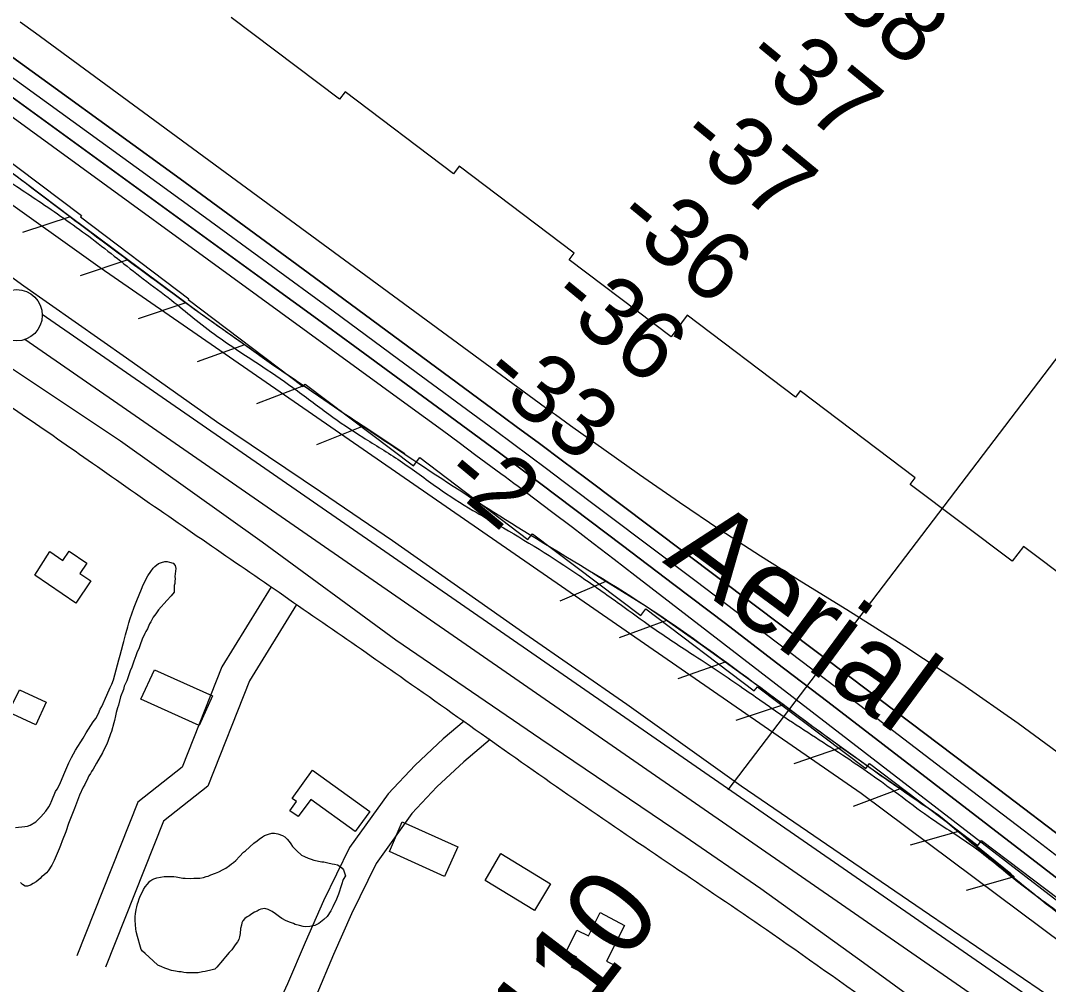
# Model space of a CAD drawing. Extents: x 3887375 to 3925618, y 296674 to 322633.
# Drawn here: x 3892222 to 3893221, y 311534 to 312470 of the extents above; entities that cross this region are included whole.
import ezdxf

# ---------------------------------------------------------------- set-up
doc = ezdxf.new("R2010")
doc.units = 0
for name, color, linetype in [('V-BLDG-OTLN', 7, 'Continuous'), ('V-LEVE-TOET', 7, 'Continuous'), ('V-RIVR-EDGE', 7, 'Continuous'), ('V-RIVR-IDEN', 7, 'Continuous'), ('V-RIVR-RANG', 7, 'Continuous'), ('V-RIVR-RANG-IDEN', 7, 'Continuous'), ('V-ROAD-CNTR', 7, 'Continuous'), ('V-RRAP-FSHR', 7, 'Continuous'), ('V-RRAP-RVMT', 7, 'Continuous'), ('V-SITE-VEGE', 7, 'Continuous'), ('V-SURV-LINE', 7, 'Continuous'), ('V-TOPO-DPTH', 7, 'Continuous'), ('V-TOPO-MINR', 7, 'Continuous')]:
    doc.layers.add(name, color=color, linetype=linetype)

msp = doc.modelspace()

# ---------------------------------------------------------------- linework, layer by layer
at = {"layer": 'V-BLDG-OTLN'}
for points in [[(3892236.46, 311931.08), (3892250.99, 311954.13), (3892263.64, 311945.47), (3892269.81, 311954.48), (3892286.89, 311942.78), (3892280.11, 311932.88), (3892290.85, 311925.52), (3892276.07, 311903.94)], [(3892352.7, 311839.17), (3892408.97, 311813.8), (3892396.08, 311785.19), (3892339.51, 311810.69)], [(3892221.56, 311819.8), (3892247.45, 311807.8), (3892237.28, 311785.86), (3892210.85, 311798.12)], [(3892561.98, 311701.53), (3892547.62, 311682.19), (3892504.42, 311713.3), (3892492.35, 311696.54), (3892484.31, 311702.33), (3892490.7, 311711.19), (3892486.37, 311714.3), (3892506.14, 311741.75)], [(3892593.35, 311691.52), (3892647.36, 311667.2), (3892634.4, 311638.43), (3892580.85, 311662.54)], [(3892673.97, 311634.35), (3892689.05, 311660.58), (3892737.52, 311631.4), (3892721.91, 311605.48)], [(3892809.42, 311590.93), (3892792.01, 311556.2), (3892802.45, 311550.96), (3892794.51, 311535.11), (3892782.81, 311540.98), (3892781.54, 311538.46), (3892757.98, 311550.26), (3892762.9, 311560.06), (3892752.57, 311565.23), (3892763.12, 311586.27), (3892774.26, 311580.69), (3892785.71, 311603.53)]]:
    msp.add_lwpolyline(points, close=True, dxfattribs=at)
at = {"layer": 'V-LEVE-TOET'}
for points in [[(3891470.84, 312662.89), (3891560.54, 312610.95), (3891672.72, 312538.88), (3891789.15, 312457.06), (3891908.44, 312364.28), (3891989.87, 312296.2), (3892058.03, 312243.98), (3892194.92, 312144.74), (3892319.54, 312061.78), (3892457.42, 311963.54), (3892587.1, 311868.44), (3892728.16, 311772.22), (3892868.41, 311677.19), (3892941.75, 311626.8), (3893041.76, 311554.85), (3893157.21, 311470.62), (3893331.95, 311347.69), (3893386.65, 311309.75), (3893477.31, 311234.74), (3893652.21, 311086.68), (3893804.29, 310952.63), (3893919.11, 310842.87), (3893996.64, 310761.99)], [(3894071.67, 310798.13), (3893995, 310874), (3893912.31, 310958.98), (3893872.09, 310996.1), (3893832.49, 311030.65), (3893774.46, 311077.88), (3893657.88, 311175.96), (3893542.29, 311273.85), (3893422.69, 311375.69), (3893387.3, 311405.29), (3893373.9, 311415.94), (3893344.14, 311437.02), (3893212.28, 311528.44), (3893105.6, 311601.13), (3893018.9, 311660.42), (3892922.81, 311726.22), (3892811.52, 311805.64), (3892712.43, 311874.2), (3892583.76, 311964.64), (3892514.04, 312012.12), (3892412.96, 312080.27), (3892325.45, 312142.14), (3892225.56, 312211.89), (3892134.64, 312277.73)]]:
    msp.add_lwpolyline(points, dxfattribs=at)
at = {"layer": 'V-RIVR-EDGE'}
msp.add_spline([(3891467.98, 312833.96), (3891486.98, 312822.05), (3891534.01, 312792.8), (3891594.13, 312753.8), (3891650.38, 312718.69), (3891687.23, 312694.81), (3891715.84, 312678.71), (3891775.97, 312641.17), (3891829.3, 312607.04), (3891872.45, 312576.34), (3891897.65, 312554.91), (3891920.44, 312540.28), (3891948.54, 312515.93), (3892002.83, 312474.52), (3892042.08, 312440.43), (3892073.59, 312415.58), (3892102.19, 312395.6), (3892133.21, 312371.24), (3892200.11, 312321.54), (3892242.77, 312292.79), (3892291.73, 312258.18), (3892341.66, 312219.21), (3892369.29, 312198.26), (3892390.13, 312181.21), (3892413.88, 312163.18), (3892453.63, 312136.38), (3892487.09, 312113.47), (3892521.99, 312087.64), (3892554.96, 312065.22), (3892591.32, 312042.31), (3892628.16, 312015.99), (3892662.1, 311994.06), (3892686.84, 311979.91), (3892764.9, 311931.15), (3892805.14, 311902.89), (3892836.17, 311880.47), (3892877.86, 311852.69), (3892924.41, 311821.49), (3892965.13, 311793.23), (3893024.77, 311754.23), (3893079.06, 311715.73), (3893108.15, 311694.29), (3893146.45, 311668.94), (3893184.74, 311638.74), (3893227.88, 311606.09), (3893285.08, 311562.73), (3893338.89, 311523.75), (3893381.55, 311493.05), (3893441.66, 311449.68), (3893482.38, 311419.95), (3893505.63, 311395.61), (3893524.53, 311379.05), (3893555.07, 311358.1), (3893588.51, 311330.33), (3893620.5, 311305.49), (3893676.23, 311256.3), (3893730.02, 311212.46), (3893771.69, 311174.96), (3893804.16, 311145.26), (3893965.04, 311005.48), (3893991.69, 310979.19), (3894015.41, 310950.48), (3894041.09, 310924.19), (3894068.7, 310897.9)], degree=3, dxfattribs=at)
at = {"layer": 'V-RIVR-RANG'}
msp.add_line((3892910.08, 311722.47), (3893249.22, 312168.1), dxfattribs=at)
at = {"layer": 'V-ROAD-CNTR'}
for points in [[(3892465.97, 311919.7), (3892418.1, 311841.98), (3892379.53, 311744.67), (3892336.49, 311710.63), (3892277.18, 311561.2)], [(3892490.67, 311902.6), (3892445.02, 311828.49), (3892404.46, 311726.13), (3892361.41, 311692.09), (3892305.06, 311550.13)], [(3892653.42, 311789.44), (3892633.21, 311772.21), (3892605.79, 311746.62), (3892579.59, 311718.63), (3892542.28, 311666.44), (3892516.84, 311614.88), (3892498.98, 311574.38), (3892481.93, 311534.01), (3892467.13, 311501.72), (3892460.06, 311465.88), (3892464.09, 311419.86)], [(3892678.71, 311771.58), (3892653.19, 311749.82), (3892627, 311725.37), (3892602.84, 311699.57), (3892568.11, 311650.98), (3892544.03, 311602.19), (3892526.53, 311562.49), (3892509.39, 311521.92), (3892495.87, 311492.44), (3892490.31, 311464.26), (3892493.97, 311422.48)]]:
    msp.add_lwpolyline(points, dxfattribs=at)
msp.add_spline([(3891930.71, 312305.17), (3892016.94, 312237.42), (3892090.97, 312173.45), (3892154.3, 312132.93), (3892292.49, 312039.88), (3892440.64, 311937.24), (3892591.28, 311832.93), (3892771.43, 311706.32), (3892952.89, 311582.91), (3893068.84, 311500.71)], degree=3, dxfattribs=at)
at = {"layer": 'V-RRAP-FSHR'}
for p, q in [((3892270.78, 312279.32), (3892224.38, 312264.11)), ((3892326.86, 312237.43), (3892280.55, 312221.93)), ((3892383.13, 312195.79), (3892336.83, 312180.3)), ((3892439.97, 312154.95), (3892393.96, 312138.6)), ((3892497.45, 312115), (3892451.79, 312097.69)), ((3892555.48, 312075.86), (3892510.06, 312057.94)), ((3892791.37, 311925.07), (3892746.45, 311905.94)), ((3892850.11, 311887.03), (3892804.27, 311870.2)), ((3892907.26, 311846.61), (3892861.13, 311830.58)), ((3892963.73, 311805.26), (3892917.4, 311789.82)), ((3893020.19, 311763.88), (3892974.05, 311747.89)), ((3893077.31, 311723.43), (3893031.54, 311706.41)), ((3893133.8, 311682.17), (3893086.86, 311668.72)), ((3893188.19, 311638.11), (3893141.25, 311624.65))]:
    msp.add_line(p, q, dxfattribs=at)
for points in [[(3891468.38, 312810.08), (3891592.07, 312735.45), (3892299.93, 312230.23), (3893039.21, 311719.28), (3893631.65, 311277.12), (3894117.75, 310846), (3894636.93, 310371.58), (3895241.96, 309786.83), (3895348.82, 309658.26), (3895604.32, 309398.25), (3896430.18, 308555.06), (3897023.94, 307973.73), (3897641.56, 307335.08), (3898033.61, 306930.91), (3898562.18, 306317.87), (3899280.35, 305434.23), (3899629.7, 304981.52), (3900046.19, 304414.8), (3900422.65, 303959.37), (3901188.76, 303011.8), (3901775.81, 302279.78)], [(3892270.78, 312279.32), (3892228.16, 312311.27), (3892214.81, 312321.36)], [(3892326.86, 312237.43), (3892312.36, 312248.16), (3892270.78, 312279.32)], [(3892383.13, 312195.79), (3892326.86, 312237.43)], [(3892439.97, 312154.95), (3892396.96, 312185.57), (3892383.13, 312195.79)], [(3892497.45, 312115), (3892466.5, 312136.07), (3892439.97, 312154.95)], [(3892555.48, 312075.86), (3892537.08, 312088.03), (3892497.45, 312115)], [(3892595.83, 312049.2), (3892555.48, 312075.86)], [(3892791.37, 311925.07), (3892779.01, 311932.78)], [(3892850.11, 311887.03), (3892830.41, 311900.74), (3892791.37, 311925.07)], [(3892907.26, 311846.61), (3892882.78, 311864.28), (3892850.11, 311887.03)], [(3892963.73, 311805.26), (3892934.52, 311826.93), (3892907.25, 311846.61)], [(3893020.19, 311763.88), (3892992.52, 311783.9), (3892963.73, 311805.26)], [(3893077.31, 311723.43), (3893051.01, 311741.57), (3893020.19, 311763.88)], [(3893188.19, 311638.11), (3893184.85, 311640.81), (3893133.8, 311682.17), (3893114.78, 311697.57), (3893082.89, 311719.57), (3893077.31, 311723.43)]]:
    msp.add_lwpolyline(points, dxfattribs=at)
for points in [[(3893114.78, 311697.57), (3893051.01, 311741.57), (3892934.52, 311826.93), (3892830.41, 311900.74), (3892716.58, 311970.79), (3892537.08, 312088.03), (3892396.96, 312185.57), (3892228.16, 312311.27), (3892082.04, 312421.65), (3891952.19, 312519.08)], [(3894693.57, 310343.47), (3894636.16, 310402.03), (3894583.88, 310450.27), (3894539.33, 310488.07), (3894475.19, 310544.65), (3894335.29, 310653.91), (3894243.97, 310732.33), (3894177.91, 310791.34), (3894063.4, 310901.68), (3893962.88, 310997.56), (3893817.75, 311132.76), (3893736.38, 311204.28), (3893588.1, 311328.9), (3893395.57, 311482.54), (3893254.93, 311584.04), (3893114.78, 311697.57)]]:
    msp.add_spline(points, degree=3, dxfattribs=at)
at = {"layer": 'V-RRAP-RVMT'}
for p, q in [((3892532.53, 312393.54), (3892427.21, 312473.14)), ((3892537.92, 312400.85), (3892532.53, 312393.54)), ((3892643.31, 312321.22), (3892537.92, 312400.85)), ((3892182.7, 312355.27), (3892281.63, 312280.54)), ((3892648.7, 312328.46), (3892643.31, 312321.22)), ((3892760.45, 312243.93), (3892648.7, 312328.46)), ((3892281.63, 312280.54), (3892280.67, 312279.33)), ((3892280.67, 312279.33), (3892385.9, 312199.67)), ((3892755.75, 312237.59), (3892760.45, 312243.93)), ((3892854.64, 312162.86), (3892755.75, 312237.59)), ((3892385.9, 312199.67), (3892385.41, 312198.95)), ((3892385.41, 312198.95), (3892497.11, 312114.56)), ((3892870.34, 312183.74), (3892854.64, 312162.86)), ((3892975.59, 312104.1), (3892870.34, 312183.74)), ((3892497.11, 312114.56), (3892498.98, 312116.91)), ((3892498.98, 312116.91), (3892604.25, 312037.4)), ((3892980.22, 312110.17), (3892975.59, 312104.1)), ((3893091.83, 312025.72), (3892980.22, 312110.17)), ((3892604.25, 312037.4), (3892610.4, 312045.46)), ((3892610.4, 312045.46), (3892715.53, 311965.82)), ((3893087.06, 312019.38), (3893091.83, 312025.72)), ((3893186.02, 311944.71), (3893087.06, 312019.38)), ((3892715.53, 311965.82), (3892719.89, 311971.47)), ((3892719.89, 311971.47), (3892825.22, 311891.9)), ((3893196.94, 311959.04), (3893186.02, 311944.71)), ((3893302.33, 311879.48), (3893196.94, 311959.04)), ((3892825.22, 311891.9), (3892830.06, 311898.31)), ((3892830.06, 311898.31), (3892935.4, 311818.8)), ((3892935.4, 311818.8), (3892938.51, 311822.8)), ((3892938.51, 311822.8), (3893043.77, 311743.16)), ((3893043.77, 311743.16), (3893047.44, 311748.05)), ((3893047.44, 311748.05), (3893152.74, 311668.48)), ((3893152.74, 311668.48), (3893156.4, 311673.3)), ((3893156.4, 311673.3), (3893255.3, 311598.5))]:
    msp.add_line(p, q, dxfattribs=at)
at = {"layer": 'V-SITE-VEGE'}
for points in [[(3892275.89, 311761.12), (3892283.48, 311772.8), (3892286.08, 311777.84), (3892293.15, 311788.72), (3892295.5, 311791.91), (3892298.12, 311796.68), (3892299.94, 311800.92), (3892301.51, 311803.57), (3892306.19, 311814.7), (3892309.58, 311822.13), (3892311.14, 311825.31), (3892312.7, 311829.55), (3892318.13, 311848.87), (3892319.15, 311853.37), (3892320.44, 311858.4), (3892322.25, 311864.49), (3892322.76, 311866.87), (3892324.57, 311873.23), (3892325.08, 311875.61), (3892326.64, 311880.9), (3892327.67, 311884.88), (3892328.96, 311889.11), (3892330.52, 311893.61), (3892332.85, 311899.97), (3892335.45, 311906.6), (3892339.87, 311917.72), (3892341.7, 311921.7), (3892346.13, 311930.45), (3892349.01, 311934.7), (3892351.37, 311937.88), (3892352.94, 311939.48), (3892356.63, 311942.41), (3892359.53, 311943.48), (3892362.69, 311944.3), (3892364.81, 311944.31), (3892367.19, 311943.8), (3892370.63, 311942.77), (3892372.76, 311940.4), (3892373.31, 311937.5), (3892372.3, 311929.83), (3892372.58, 311927.72), (3892372.33, 311925.34), (3892372.34, 311923.22), (3892371.83, 311921.1), (3892371.84, 311918.73), (3892371.6, 311914.76)], [(3892371.6, 311914.76), (3892368.72, 311911.04), (3892364.79, 311906.52), (3892356.66, 311897.48), (3892355.34, 311895.63), (3892354.04, 311893.5), (3892351.42, 311890.31), (3892349.07, 311885.81), (3892347.76, 311883.95), (3892345.68, 311878.91), (3892344.11, 311876.53), (3892343.33, 311874.41), (3892340.72, 311868.84), (3892338.64, 311863.54), (3892337.6, 311860.63), (3892335.52, 311855.86), (3892334.48, 311852.68), (3892332.4, 311847.64), (3892330.59, 311841.82), (3892329.03, 311838.11), (3892325.66, 311828.57), (3892323.31, 311823.27), (3892322.54, 311820.1), (3892319.68, 311812.94), (3892317.62, 311805), (3892316.58, 311802.35), (3892315.29, 311797.59), (3892314.78, 311794.41), (3892313.75, 311789.91), (3892312.98, 311787.53), (3892310.92, 311779.32), (3892309.87, 311776.94), (3892307.28, 311769.52), (3892305.98, 311766.34), (3892303.89, 311762.1), (3892302.06, 311758.65), (3892296.32, 311748.57), (3892293.19, 311742.74), (3892291.35, 311740.35), (3892290.57, 311738.49), (3892288.74, 311736.1), (3892287.96, 311733.98), (3892284.83, 311727.89), (3892283.26, 311725.23), (3892279.87, 311717.28), (3892274.94, 311704.3), (3892268.96, 311689.73), (3892266.37, 311681.78), (3892262.98, 311673.04), (3892261.43, 311668.54), (3892260.13, 311665.36), (3892255.18, 311653.96), (3892254.14, 311651.84), (3892252.83, 311649.45), (3892249.44, 311643.88), (3892247.6, 311642.02), (3892244.97, 311639.62), (3892242.87, 311638.03), (3892241.56, 311636.43), (3892239.45, 311634.83), (3892237.61, 311633.23), (3892234.72, 311631.63), (3892232.08, 311630.03), (3892229.18, 311628.95), (3892226.81, 311628.94), (3892224.42, 311630.51), (3892222.29, 311632.61)], [(3892217.71, 311685.96), (3892226.69, 311686.81), (3892229.07, 311687.35), (3892231.7, 311688.16), (3892237.23, 311691.37), (3892242.22, 311696.42), (3892246.94, 311702.01), (3892249.82, 311705.99), (3892251.13, 311708.37), (3892252.95, 311712.09), (3892256.6, 311720.83), (3892258.16, 311723.22), (3892260.78, 311727.99), (3892264.42, 311737.53), (3892266.5, 311742.04), (3892269.36, 311748.92), (3892271.97, 311753.96), (3892275.89, 311761.12)], [(3892393.51, 311636.63), (3892396.68, 311636.92), (3892400.37, 311637.47), (3892402.75, 311638.28), (3892404.86, 311638.82), (3892407.49, 311639.9), (3892411.97, 311641.51), (3892415.14, 311642.85), (3892419.35, 311645.26), (3892421.98, 311646.6), (3892425.67, 311649), (3892427.5, 311650.6), (3892429.35, 311651.93), (3892431.71, 311654.06), (3892435.39, 311657.78), (3892439.06, 311662.03), (3892441.16, 311663.37), (3892449.31, 311670.82), (3892452.46, 311672.96), (3892454.3, 311674.55), (3892457.46, 311676.95), (3892459.56, 311678.29), (3892463.52, 311679.37), (3892466.69, 311680.45), (3892469.33, 311680.47), (3892472.5, 311679.96), (3892477.01, 311678.14), (3892479.39, 311676.83), (3892481.52, 311674.73), (3892483.65, 311672.37), (3892484.99, 311670.26), (3892486.86, 311667.63), (3892490.85, 311663.43), (3892495.63, 311659.23), (3892498.55, 311657.66), (3892501.99, 311656.1), (3892504.9, 311655.33), (3892507.55, 311654.29), (3892515.23, 311652.75), (3892517.34, 311652.5), (3892521.05, 311651.73), (3892525.28, 311650.71), (3892527.4, 311650.45), (3892530.58, 311649.68), (3892532.96, 311648.11), (3892535.09, 311646.54), (3892536.16, 311644.7), (3892538.31, 311639.16)], [(3892538.31, 311639.16), (3892535.95, 311635.45), (3892534.4, 311630.15), (3892531.55, 311621.15), (3892528.95, 311614.79), (3892526.86, 311611.08), (3892526.08, 311608.96), (3892524, 311604.98), (3892520.33, 311599.67), (3892517.18, 311596.48), (3892512.45, 311592.75), (3892508.5, 311590.87), (3892503.48, 311589.78), (3892499.52, 311589.49), (3892497.14, 311589.74), (3892493.7, 311590.78), (3892489.46, 311591.81), (3892487.61, 311592.59), (3892484.7, 311593.62), (3892480.45, 311595.45), (3892476.48, 311597.53), (3892474.09, 311599.11), (3892470.1, 311602.25), (3892466.92, 311604.34), (3892462.94, 311606.17), (3892459.77, 311607.2), (3892456.07, 311606.65), (3892454.23, 311605.84), (3892452.38, 311604.78), (3892449.75, 311603.7), (3892447.12, 311602.1), (3892444.48, 311600.23), (3892442.64, 311599.16), (3892440.54, 311597.56), (3892438.44, 311595.43), (3892437.66, 311593.32), (3892437.15, 311591.2), (3892436.11, 311587.76), (3892435.88, 311583), (3892435.37, 311579.82), (3892434.59, 311577.18), (3892433.29, 311574.79), (3892430.93, 311571.87), (3892427.79, 311567.09), (3892425.16, 311564.43), (3892421.49, 311560.18), (3892420.18, 311558.32), (3892418.87, 311556.73), (3892413.36, 311550.35), (3892411.26, 311548.48), (3892408.62, 311547.67), (3892402.03, 311546.04), (3892399.39, 311545.76), (3892395.16, 311544.94), (3892392.52, 311544.66), (3892388.29, 311544.63), (3892383.8, 311544.87), (3892381.16, 311545.11), (3892378.51, 311545.62), (3892376.13, 311545.88), (3892372.96, 311546.38), (3892369.25, 311547.15), (3892364.75, 311548.71), (3892362.63, 311549.22), (3892359.71, 311550.52), (3892356, 311552.35), (3892351.22, 311556.28), (3892343.51, 311563.63), (3892340.85, 311565.73), (3892339.78, 311567.57), (3892338.98, 311569.68), (3892336, 311579.97), (3892334.91, 311584.98), (3892334.63, 311587.62), (3892334.08, 311591.32), (3892333.79, 311595.81), (3892333.76, 311599.51), (3892334.27, 311602.15), (3892334.77, 311606.39), (3892335.55, 311608.77), (3892336.06, 311611.68), (3892336.84, 311613.54), (3892337.61, 311616.71), (3892339.18, 311619.89), (3892340.22, 311622.28), (3892342.04, 311625.73), (3892343.61, 311628.38), (3892345.71, 311630.77), (3892348.07, 311633.69), (3892350.18, 311635.29), (3892352.02, 311636.1), (3892354.92, 311637.17), (3892362.05, 311638.28), (3892371.3, 311638.34), (3892373.68, 311638.09), (3892376.85, 311637.31), (3892380.29, 311636.81), (3892382.41, 311636.82), (3892387.17, 311636.33), (3892390.86, 311636.61), (3892393.51, 311636.63)]]:
    msp.add_lwpolyline(points, dxfattribs=at)
at = {"layer": 'V-SURV-LINE'}
for points in [[(3892243.54, 312184.7), (3893320.18, 311440.26)], [(3893303.12, 311415.58), (3892226.48, 312160.02)]]:
    msp.add_lwpolyline(points, dxfattribs=at)
msp.add_circle((3892218.58, 312183.72), 25, dxfattribs=at)
at = {"layer": 'V-TOPO-DPTH'}
for points in [[(3892173.55, 312463.92), (3892252.5, 312406.87), (3892315.03, 312361.56), (3892377.47, 312316.12), (3892439.78, 312270.51), (3892502, 312224.78), (3892681.57, 312092.42), (3892704.17, 312075.71), (3892726.74, 312058.96), (3892749.26, 312042.14), (3892771.74, 312025.28), (3893029.68, 311831.28), (3893101.32, 311777.26), (3893172.86, 311723.12), (3893244.27, 311668.81)], [(3893244.27, 311668.81), (3893172.86, 311723.12), (3893101.32, 311777.26), (3893029.68, 311831.28), (3892771.74, 312025.28), (3892749.26, 312042.14), (3892726.74, 312058.96), (3892704.17, 312075.71), (3892681.57, 312092.42), (3892502, 312224.78), (3892439.78, 312270.51), (3892377.47, 312316.12), (3892315.03, 312361.56), (3892252.5, 312406.87), (3892173.55, 312463.92)], [(3892222.2, 312468.93), (3892237, 312458.09), (3892737.33, 312090.67), (3892742.19, 312087.12), (3892747.06, 312083.59), (3892751.95, 312080.07), (3892756.85, 312076.58), (3892824.07, 312028.88), (3892862.85, 312001.94), (3892901.97, 311975.53), (3892941.62, 311949.91), (3892981.62, 311924.82), (3893025.48, 311897.91), (3893081.76, 311862.26), (3893137.32, 311825.57), (3893191.81, 311787.3), (3893245.59, 311747.98)], [(3892222.2, 312468.93), (3892237, 312458.09), (3892737.33, 312090.67), (3892742.19, 312087.12), (3892747.06, 312083.59), (3892751.95, 312080.07), (3892756.85, 312076.58), (3892824.07, 312028.88), (3892862.85, 312001.94), (3892901.97, 311975.53), (3892941.62, 311949.91), (3892981.62, 311924.82), (3893025.48, 311897.91), (3893081.76, 311862.26), (3893137.32, 311825.57), (3893191.81, 311787.3), (3893245.59, 311747.98)], [(3893631.49, 311327.49), (3893006.94, 311807.96), (3892957.2, 311846.13), (3892907.38, 311884.2), (3892857.47, 311922.15), (3892807.49, 311960), (3892727.98, 312020.06), (3892717.69, 312027.8), (3892707.38, 312035.52), (3892697.04, 312043.21), (3892686.69, 312050.87), (3892627.5, 312094.48), (3892587.51, 312123.89), (3892547.47, 312153.24), (3892507.38, 312182.51), (3892467.25, 312211.73), (3892128.34, 312457.89)]]:
    msp.add_lwpolyline(points, dxfattribs=at)
at = {"layer": 'V-TOPO-MINR'}
for points in [[(3892173.55, 312463.92), (3892252.5, 312406.87), (3892315.03, 312361.56), (3892377.47, 312316.12), (3892439.78, 312270.51), (3892502, 312224.78), (3892681.57, 312092.42), (3892704.17, 312075.71), (3892726.74, 312058.96), (3892749.26, 312042.14), (3892771.74, 312025.28), (3893029.68, 311831.28), (3893101.32, 311777.26), (3893172.86, 311723.12), (3893244.27, 311668.81)], [(3892222.2, 312468.93), (3892237, 312458.09), (3892737.33, 312090.67), (3892742.19, 312087.12), (3892747.06, 312083.59), (3892751.95, 312080.07), (3892756.85, 312076.58), (3892824.07, 312028.88), (3892862.85, 312001.94), (3892901.97, 311975.53), (3892941.62, 311949.91), (3892981.62, 311924.82), (3893025.48, 311897.91), (3893081.76, 311862.26), (3893137.32, 311825.57), (3893191.81, 311787.3), (3893245.59, 311747.98)], [(3892106.4, 312455.01), (3892599.59, 312095.87), (3892615.98, 312083.91), (3892632.36, 312071.94), (3892648.72, 312059.93), (3892665.06, 312047.91), (3892689.25, 312030.09), (3892693.48, 312026.96), (3892697.71, 312023.82), (3892701.93, 312020.66), (3892706.13, 312017.49), (3892738.38, 311993.1), (3892758.68, 311977.7), (3892778.96, 311962.27), (3892799.19, 311946.77), (3892819.4, 311931.25), (3893833.55, 311149.73)], [(3892128.34, 312457.89), (3892467.25, 312211.73), (3892507.38, 312182.51), (3892547.47, 312153.24), (3892587.51, 312123.89), (3892627.5, 312094.48), (3892686.69, 312050.87), (3892697.04, 312043.21), (3892707.38, 312035.52), (3892717.69, 312027.8), (3892727.98, 312020.06), (3892807.49, 311960), (3892857.47, 311922.15), (3892907.38, 311884.2), (3892957.2, 311846.13), (3893006.94, 311807.96), (3893631.49, 311327.49)], [(3892150.71, 312460.86), (3892334.69, 312327.58), (3892398.63, 312281.14), (3892462.48, 312234.6), (3892526.23, 312187.9), (3892589.9, 312141.09), (3892684.12, 312071.64), (3892700.6, 312059.46), (3892717.05, 312047.24), (3892733.47, 312034.96), (3892749.85, 312022.65), (3892877.74, 311926.21), (3892957.98, 311865.56), (3893038.11, 311804.76), (3893118.08, 311743.76), (3893197.94, 311682.62), (3893429.78, 311504.66)]]:
    msp.add_lwpolyline(points, dxfattribs=at)

# ---------------------------------------------------------------- texts
at = {"layer": 'V-RIVR-IDEN'}
msp.add_text('Aerial', height=83, rotation=323.56796, dxfattribs=at).set_placement((3892845.48, 311944.05))
at = {"layer": 'V-RIVR-RANG'}
for s, rotation, p in [('-38', 320.58558, (3892988.06, 312504.87)), ('-37', 320.58558, (3892922.75, 312429.11)), ('-37', 320.58558, (3892859.06, 312352)), ('-36', 320.58558, (3892797.42, 312273.23)), ('-36', 320.58558, (3892733.74, 312196.13)), ('-33', 320.58558, (3892667.61, 312121.04)), ('-2', 320.29833, (3892629.64, 312023.15))]:
    msp.add_text(s, height=67, rotation=rotation, dxfattribs=at).set_placement(p)
at = {"layer": 'V-RIVR-RANG-IDEN'}
msp.add_text('U-110', height=83, rotation=52.58633, dxfattribs=at).set_placement((3892663.88, 311362.94))

doc.saveas('drawing.dxf')
